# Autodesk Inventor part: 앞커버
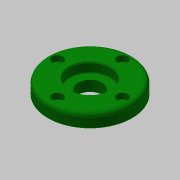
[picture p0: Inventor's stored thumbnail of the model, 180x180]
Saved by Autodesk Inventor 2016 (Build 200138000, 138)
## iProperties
Created: 2015-09
Part Number: 앞커버
Material: 알루미늄 6061
Document SubType Name: Modeling
Designer: mduedu
Density: 1 g/cm^3
Appearance: 진녹색
Author: mduedu
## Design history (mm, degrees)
sketch "스케치1"
  geometry: L1 (0, 7.5)-(0, -7.5); L2 (0, 7.5)-(31, 7.5); L3 (31, 7.5)-(31, -2.5); L4 (31, -2.5)-(17.5, -2.5); L5 (17.5, -2.5)-(17.5, -7.5); L6 (17.5, -7.5)-(0, -7.5); 2 further points
  constraints: 12 end point, 2 parallel, 2 perpendicular, 1 coincident, 1 horizontal, 1 midpoint, 1 vertical
  dimensions: "d0" = 15 distance of L1.start L1.end; "d1" = 62 diameter of L3 L1; "d2" = 35 diameter of L5 L1; "d3" = 10 distance of L2.end L3.end
revolve "회전1" sketch "스케치1" stored, may be unused: angle "d4" = 90 deg
hole "구멍1" diameter "d7" = 30; stored, may be unused: countersink angle "d11" = 90 deg, drill point angle "d13" = 0 deg; dims "d8" = 6, "d9" = 4, "d10" = 2, "d12" = 7.3, "d46" = 10, "d47" = 10
hole "구멍2" diameter "d16" = 18; stored, may be unused: countersink angle "d20" = 90 deg, drill point angle "d22" = 0 deg; dims "d14" = 10, "d15" = 10, "d17" = 6, "d18" = 4, "d19" = 2, "d21" = 7.3
fillet "모깎기2" dims "d48" = 3
chamfer "모따기2" distance "d26" = 0.7; stored, may be unused: second distance "d27" = 2, angle "d28" = 30 deg
fillet "모깎기1" dims "d29" = 0.3
sketch "스케치4" dims "d49" = 48
  geometry: 3 further points
  constraints: 2 vertical alignment, 1 coincident, 2 other
hole "구멍4" sketch "스케치4" at (0, 24) diameter "d50" = 4.5; stored, may be unused: countersink angle "d54" = 90 deg, drill point angle "d56" = 118 deg; dims "d51" = 6, "d52" = 8, "d53" = 4.4, "d55" = 8
chamfer "모따기3" distance "d43" = 1; stored, may be unused: second distance "d44" = 2, angle "d45" = 45 deg
node "솔리드1"
pattern_circular "원형 패턴1" dims angle "d58" = 360 deg
